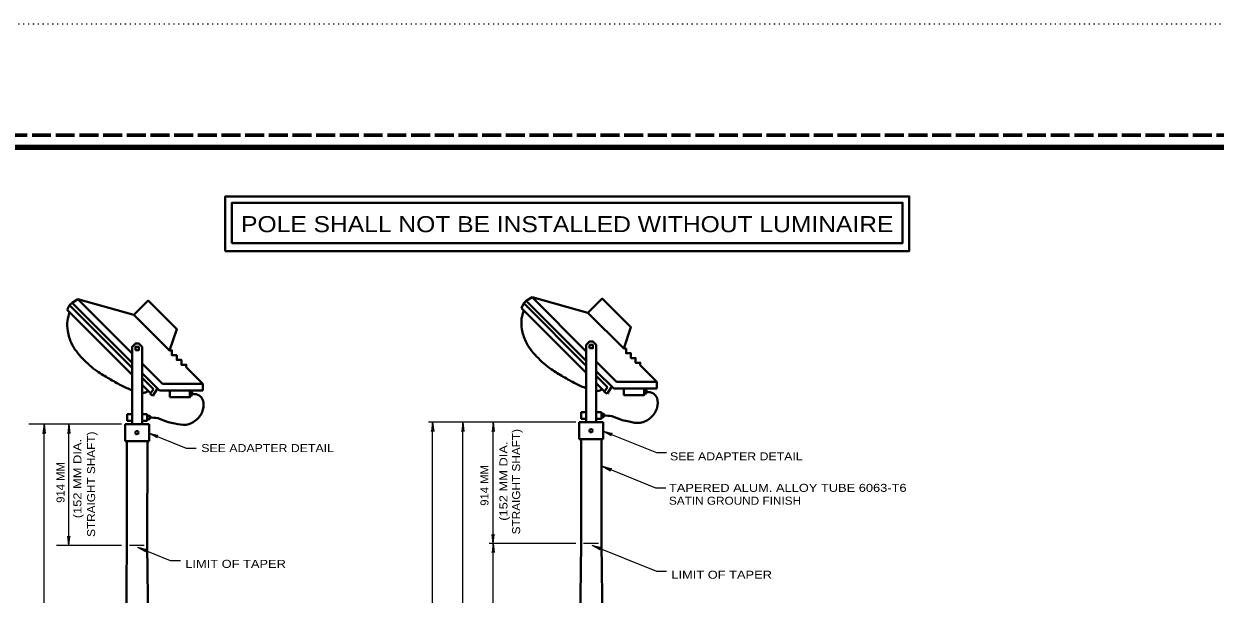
# Model space of a CAD drawing. Extents: x 312583 to 312854, y 144419 to 144597.
# Drawn here: x 312682.7 to 312795.8, y 144542.7 to 144596.8 of the extents above; entities that cross this region are included whole.
import ezdxf
from ezdxf.enums import TextEntityAlignment as Align

# ---------------------------------------------------------------- set-up
doc = ezdxf.new("R2010")
doc.units = 0
doc.header["$LTSCALE"] = 0.3
doc.linetypes.add('DOTTED', pattern=[1.5, 0.3, -1.2])
doc.linetypes.add('LONG_DASHED', pattern=[7.5, 6, -1.5])
for name, color, linetype, lineweight in [('1', 7, 'Continuous', 40), ('2', 7, 'Continuous', 13), ('63', 7, 'DOTTED', 13)]:
    doc.layers.add(name, color=color, linetype=linetype, lineweight=lineweight)

msp = doc.modelspace()

# ---------------------------------------------------------------- linework, layer by layer
at = {"layer": '1'}
for p, q in [((312687.0228, 144570.084), (312692.9568, 144564.1576)), ((312687.8125, 144570.6436), (312687.2528, 144570.3063)), ((312687.2528, 144570.3063), (312692.9568, 144564.6023)), ((312693.1178, 144569.1716), (312687.8125, 144570.6436)), ((312687.8125, 144570.6436), (312692.9568, 144565.507)), ((312729.9367, 144569.8156), (312736.0853, 144563.6593)), ((312730.159, 144570.268), (312736.0853, 144564.3416)), ((312730.9487, 144570.8353), (312730.389, 144570.4903)), ((312730.389, 144570.4903), (312736.0853, 144564.794)), ((312736.254, 144569.3633), (312730.9487, 144570.8353)), ((312730.9487, 144570.8353), (312736.0853, 144565.691)), ((312686.8005, 144569.6316), (312692.9568, 144563.4753)), ((312693.1178, 144569.1716), (312696.5065, 144565.7906)), ((312736.254, 144569.3633), (312739.6427, 144565.9746)), ((312693.9152, 144558.791), (312693.9152, 144566.1356)), ((312737.0437, 144558.975), (312737.0437, 144566.3196)), ((312693.9152, 144564.5486), (312695.8318, 144562.6243)), ((312698.0935, 144564.2036), (312699.6652, 144562.6243)), ((312737.0437, 144564.7326), (312738.968, 144562.816)), ((312741.222, 144564.3876), (312742.8013, 144562.816)), ((312693.9152, 144563.644), (312695.5712, 144561.988)), ((312693.9152, 144563.1993), (312694.9732, 144562.1336)), ((312737.0437, 144563.8356), (312738.7073, 144562.172)), ((312737.0437, 144563.3833), (312738.1093, 144562.3176)), ((312693.9152, 144562.517), (312694.6972, 144561.7273)), ((312694.9732, 144562.1336), (312694.6665, 144561.6736)), ((312695.3795, 144562.1796), (312694.9348, 144561.4973)), ((312695.5712, 144561.988), (312699.6652, 144561.988)), ((312695.8318, 144562.6243), (312699.6652, 144562.6243)), ((312696.5295, 144561.988), (312696.5295, 144561.3516)), ((312699.6652, 144562.6243), (312699.6652, 144561.988)), ((312737.0437, 144562.701), (312737.8333, 144561.9113)), ((312738.1093, 144562.3176), (312737.8027, 144561.8576)), ((312738.0633, 144561.6813), (312737.8027, 144561.8576)), ((312738.5157, 144562.3636), (312738.0633, 144561.6813)), ((312738.7073, 144562.172), (312742.8013, 144562.172)), ((312738.968, 144562.816), (312742.8013, 144562.816)), ((312739.6657, 144562.172), (312739.6657, 144561.5356)), ((312742.8013, 144562.816), (312742.8013, 144562.172)), ((312694.9348, 144561.4973), (312694.6665, 144561.6736)), ((312698.4462, 144561.5126), (312698.6762, 144561.5126)), ((312741.5823, 144561.6966), (312741.8123, 144561.6966)), ((312692.4738, 144559.7493), (312692.4738, 144559.1053)), ((312692.4738, 144559.7493), (312692.9568, 144559.7493)), ((312693.9152, 144559.7493), (312694.3905, 144559.7493)), ((312694.3905, 144559.7493), (312694.3905, 144559.1053)), ((312735.61, 144559.9333), (312735.61, 144559.297)), ((312735.61, 144559.9333), (312736.0853, 144559.9333)), ((312737.0437, 144559.9333), (312737.5267, 144559.9333)), ((312737.5267, 144559.9333), (312737.5267, 144559.297)), ((312692.2975, 144558.791), (312692.2898, 144557.1963)), ((312692.2975, 144558.791), (312694.5745, 144558.7833)), ((312692.9568, 144559.1053), (312692.4738, 144559.1053)), ((312694.3905, 144559.1053), (312693.9152, 144559.1053)), ((312694.3905, 144559.2663), (312694.6282, 144559.2663)), ((312694.5745, 144558.7833), (312694.5668, 144557.1886)), ((312735.426, 144558.975), (312737.703, 144558.975)), ((312735.426, 144558.975), (312735.426, 144557.3803)), ((312736.0853, 144559.297), (312735.61, 144559.297)), ((312737.5267, 144559.297), (312737.0437, 144559.297)), ((312737.5267, 144559.4503), (312737.7643, 144559.4503)), ((312737.703, 144558.975), (312737.703, 144557.3726)), ((312735.426, 144557.3803), (312737.703, 144557.3726)), ((312735.5947, 144557.3803), (312735.6023, 144547.475)), ((312737.542, 144557.3726), (312737.5343, 144547.475)), ((312692.2898, 144557.1963), (312694.5668, 144557.1886)), ((312692.4585, 144557.1963), (312692.4662, 144547.291)), ((312694.4058, 144557.1886), (312694.3982, 144547.291)), ((312692.4662, 144547.291), (312692.3282, 144535.0856)), ((312694.3982, 144547.291), (312694.5362, 144535.0856)), ((312735.6023, 144547.475), (312735.4643, 144535.2696)), ((312737.5343, 144547.475), (312737.6723, 144535.2696))]:
    msp.add_line(p, q, dxfattribs=at)
at = {"layer": '1', "lineweight": 158}
msp.add_lwpolyline([(312616.5, 144423.1446), (312616.5, 144585.0846), (312849, 144585.0846)], dxfattribs=at)
at = {"layer": '1'}
for points in [[(312687.2528, 144570.3063), (312687.0228, 144570.084), (312686.8005, 144569.6316)], [(312693.1178, 144569.1716), (312694.4748, 144570.5286), (312697.1888, 144567.8223), (312696.5065, 144565.7906)], [(312730.389, 144570.4903), (312730.159, 144570.268), (312729.9367, 144569.8156)], [(312736.254, 144569.3633), (312737.611, 144570.7126), (312740.325, 144568.0063), (312739.6427, 144565.9746)], [(312692.9568, 144558.791), (312692.9568, 144566.1356), (312693.2712, 144566.4576), (312693.5932, 144566.4576), (312693.9152, 144566.1356)], [(312736.0853, 144558.975), (312736.0853, 144566.3196), (312736.4073, 144566.6416), (312736.7293, 144566.6416), (312737.0437, 144566.3196)], [(312696.5065, 144565.7906), (312696.7365, 144565.7906), (312696.7365, 144565.3383), (312697.1888, 144565.3383), (312697.1888, 144564.886), (312697.6412, 144564.886), (312697.6412, 144564.4336), (312698.0935, 144564.4336), (312698.0935, 144564.2036)], [(312739.6427, 144565.9746), (312739.8727, 144565.9746), (312739.8727, 144565.5223), (312740.325, 144565.5223), (312740.325, 144565.07), (312740.7773, 144565.07), (312740.7773, 144564.6176), (312741.222, 144564.6176), (312741.222, 144564.3876)], [(312698.4462, 144561.988), (312698.4462, 144561.3516), (312696.5295, 144561.3516)], [(312741.5823, 144562.172), (312741.5823, 144561.5356), (312739.6657, 144561.5356)], [(312741.5823, 144562.011), (312741.8123, 144562.011), (312741.8123, 144561.6966)], [(312698.4462, 144561.827), (312698.6762, 144561.827), (312698.6762, 144561.5126)], [(312694.3905, 144559.5883), (312694.6282, 144559.5883), (312694.6282, 144559.2663)], [(312737.5267, 144559.7723), (312737.7643, 144559.7723), (312737.7643, 144559.4503)]]:
    msp.add_lwpolyline(points, dxfattribs=at)
for points in [[(312693.2712, 144565.8136), (312693.2712, 144566.1356), (312693.5932, 144566.1356), (312693.5932, 144565.8136)], [(312736.4073, 144566.0053), (312736.4073, 144566.3196), (312736.7293, 144566.3196), (312736.7293, 144566.0053)]]:
    msp.add_lwpolyline(points, close=True, dxfattribs=at)
for centre in [(312693.412, 144557.992), (312736.5476, 144558.177)]:
    msp.add_circle(centre, 0.1597, dxfattribs=at)
for points in [[(312687.0228, 144569.4016), (312686.8158, 144568.635), (312686.8465, 144567.6153), (312687.1992, 144566.473), (312688.2418, 144565.0316), (312689.6372, 144563.8203), (312690.7718, 144563.115), (312691.9525, 144562.4633), (312692.9645, 144561.9956)], [(312730.159, 144569.5856), (312729.952, 144568.819), (312729.9827, 144567.7993), (312730.3353, 144566.657), (312731.378, 144565.2156), (312732.7657, 144564.0043), (312733.908, 144563.299), (312735.081, 144562.6473), (312736.1007, 144562.1796)], [(312693.8998, 144561.781), (312694.2295, 144561.8116), (312694.4748, 144561.9573)], [(312737.0283, 144561.965), (312737.3657, 144561.9956), (312737.611, 144562.1413)], [(312741.8123, 144561.8576), (312742.4717, 144561.7043), (312742.809, 144561.252), (312742.8243, 144560.3703), (312742.2647, 144559.458), (312741.199, 144558.9213), (312740.164, 144559.0363), (312739.5123, 144559.182), (312738.531, 144559.5423), (312737.7643, 144559.6113)], [(312698.6762, 144561.666), (312699.3355, 144561.5203), (312699.6728, 144561.068), (312699.6882, 144560.1863), (312699.1285, 144559.274), (312698.0628, 144558.7373), (312697.0278, 144558.8523), (312696.3762, 144558.998), (312695.3948, 144559.3583), (312694.6282, 144559.4273)]]:
    msp.add_spline(points, degree=3, dxfattribs=at)
at = {"layer": '2'}
for p, q in [((312691.9525, 144558.791), (312683.1489, 144558.791)), ((312684.596, 144558.791), (312684.4887, 144557.9246)), ((312684.596, 144474.4576), (312684.596, 144558.791)), ((312684.596, 144558.791), (312684.7033, 144557.9246)), ((312686.9443, 144558.791), (312686.837, 144557.9246)), ((312686.9443, 144547.291), (312686.9443, 144558.791)), ((312686.9443, 144558.791), (312687.0516, 144557.9246)), ((312735.0887, 144558.975), (312721.1123, 144558.975)), ((312721.4957, 144558.975), (312721.3883, 144558.1086)), ((312721.4957, 144474.6416), (312721.4957, 144558.975)), ((312721.4957, 144558.975), (312721.603, 144558.1086)), ((312724.3707, 144558.975), (312724.2633, 144558.1086)), ((312724.3707, 144520.6416), (312724.3707, 144558.975)), ((312724.3707, 144558.975), (312724.478, 144558.1086)), ((312727.2457, 144558.975), (312727.1383, 144558.1086)), ((312727.2457, 144558.975), (312727.353, 144558.1086)), ((312684.4887, 144557.9246), (312684.596, 144558.2006)), ((312684.7033, 144557.9246), (312684.596, 144558.2006)), ((312686.837, 144557.9246), (312686.9443, 144558.2006)), ((312687.0516, 144557.9246), (312686.9443, 144558.2006)), ((312694.5668, 144557.9476), (312695.3335, 144557.526)), ((312694.5668, 144557.9476), (312695.4102, 144557.7253)), ((312695.3335, 144557.526), (312695.1188, 144557.7253)), ((312695.4102, 144557.7253), (312695.1188, 144557.7253)), ((312721.3883, 144558.1086), (312721.4957, 144558.3846)), ((312721.603, 144558.1086), (312721.4957, 144558.3846)), ((312724.2633, 144558.1086), (312724.3707, 144558.3846)), ((312724.478, 144558.1086), (312724.3707, 144558.3846)), ((312727.1383, 144558.1086), (312727.2457, 144558.3846)), ((312727.353, 144558.1086), (312727.2457, 144558.3846)), ((312737.703, 144558.1316), (312738.4697, 144557.71)), ((312737.703, 144558.1316), (312738.5463, 144557.9093)), ((312738.4697, 144557.71), (312738.255, 144557.9093)), ((312738.5463, 144557.9093), (312738.255, 144557.9093)), ((312737.634, 144554.7966), (312738.4007, 144554.3673)), ((312737.634, 144554.7966), (312738.4773, 144554.5666)), ((312738.4007, 144554.3673), (312738.186, 144554.5743)), ((312738.4773, 144554.5666), (312738.186, 144554.5743)), ((312727.1383, 144548.3413), (312727.2457, 144548.0653)), ((312727.2457, 144547.475), (312727.1383, 144548.3413)), ((312727.353, 144548.3413), (312727.2457, 144548.0653)), ((312727.2457, 144547.475), (312727.353, 144548.3413)), ((312691.9525, 144547.291), (312685.7711, 144547.291)), ((312686.837, 144548.1573), (312686.9443, 144547.8813)), ((312686.9443, 144547.291), (312686.837, 144548.1573)), ((312687.0516, 144548.1573), (312686.9443, 144547.8813)), ((312686.9443, 144547.291), (312687.0516, 144548.1573)), ((312694.1145, 144547.291), (312692.7038, 144547.291)), ((312735.0887, 144547.475), (312726.8623, 144547.475)), ((312727.2457, 144547.475), (312727.1383, 144546.6086)), ((312727.2457, 144547.475), (312727.353, 144546.6086)), ((312737.2507, 144547.475), (312735.84, 144547.475)), ((312736.6067, 144547.314), (312742.7477, 144544.8376)), ((312736.6067, 144547.314), (312737.3657, 144546.8923)), ((312736.6067, 144547.314), (312737.45, 144547.0916)), ((312693.4705, 144547.13), (312696.5833, 144545.8747)), ((312693.4705, 144547.13), (312694.2295, 144546.7083)), ((312693.4705, 144547.13), (312694.3138, 144546.9076)), ((312694.2295, 144546.7083), (312694.0148, 144546.9076)), ((312694.3138, 144546.9076), (312694.0148, 144546.9076)), ((312727.1383, 144546.6086), (312727.2457, 144546.8846)), ((312727.353, 144546.6086), (312727.2457, 144546.8846)), ((312737.3657, 144546.8923), (312737.151, 144547.0916)), ((312737.45, 144547.0916), (312737.151, 144547.0916)), ((312696.5833, 144545.8747), (312697.5416, 144545.8747)), ((312742.7477, 144544.8376), (312743.706, 144544.8376))]:
    msp.add_line(p, q, dxfattribs=at)
at = {"layer": '2', "lineweight": 40}
for points in [[(312701.7961, 144575.2205), (312701.7961, 144580.4104), (312766.7736, 144580.4104), (312766.7736, 144575.2205)], [(312702.4339, 144575.9872), (312702.4339, 144579.8076), (312766.1357, 144579.8076), (312766.1357, 144575.9872)]]:
    msp.add_lwpolyline(points, close=True, dxfattribs=at)
at = {"layer": '2'}
for points in [[(312727.2457, 144520.6416), (312727.2457, 144547.475), (312727.2457, 144558.975)], [(312694.5668, 144557.9476), (312698.0889, 144556.5292), (312699.0472, 144556.5292)], [(312737.703, 144558.1316), (312742.7477, 144556.1), (312743.706, 144556.1)], [(312737.634, 144554.7966), (312742.6787, 144552.7573), (312743.637, 144552.7573)]]:
    msp.add_lwpolyline(points, dxfattribs=at)
at = {"layer": '63'}
msp.add_line((312601.2, 144596.7846), (312853.5, 144596.7846), dxfattribs=at)
at = {"layer": '63', "linetype": 'LONG_DASHED', "lineweight": 60}
msp.add_line((312851.75, 144586.2246), (312583.526, 144586.2246), dxfattribs=at)

# ---------------------------------------------------------------- texts
at = {"layer": '2', "width": 1.15}
msp.add_text('POLE SHALL NOT BE INSTALLED WITHOUT LUMINAIRE', height=1.52, dxfattribs=at).set_placement((312734.2833, 144577.0166), align=Align.CENTER)
at = {"layer": '2'}
for s, width, p in [('STRAIGHT SHAFT)', 1.1, (312689.4426, 144548.0979)), ('STRAIGHT SHAFT)', 1.1, (312729.8103, 144548.3395)), ('(152 MM DIA.', 1.2, (312688.1413, 144549.8701)), ('(152 MM DIA.', 1.2, (312728.6074, 144549.6287)), ('914 MM', 1.05, (312686.5357, 144551.3331)), ('914 MM', 1.05, (312726.8016, 144551.0561))]:
    msp.add_text(s, height=0.76, rotation=90, dxfattribs=dict(at, width=width)).set_placement(p)
for s, width, p in [('SEE ADAPTER DETAIL', 1.15, (312699.5264, 144556.1469)), ('SEE ADAPTER DETAIL', 1.15, (312744.0433, 144555.363)), ('TAPERED ALUM. ALLOY TUBE 6063-T6', 1.2, (312743.9437, 144552.373)), ('SATIN GROUND FINISH', 1.1, (312743.9437, 144551.153)), ('LIMIT OF TAPER', 1.2, (312698.0093, 144545.1607)), ('LIMIT OF TAPER', 1.2, (312744.1737, 144544.1313))]:
    msp.add_text(s, height=0.76, dxfattribs=dict(at, width=width)).set_placement(p)

doc.saveas('drawing.dxf')
